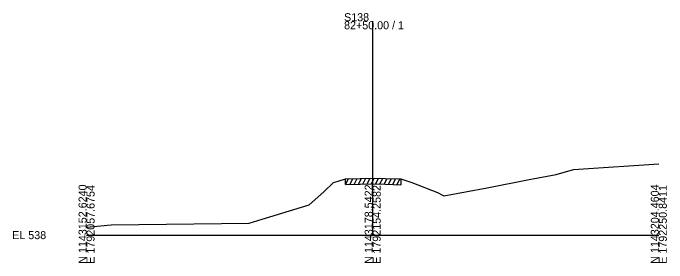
# Model space of a CAD drawing. Extents: x -26 to 1203, y -10 to 19606.
# Drawn here: x -25.7 to 202.8, y 4990.3 to 5077.5 of the extents above; entities that cross this region are included whole.
import ezdxf

# ---------------------------------------------------------------- set-up
doc = ezdxf.new("R2010")
doc.units = 0
for name, color, linetype in [('RD_EX_Driveway', 7, 'Continuous'), ('RD_GPK_XS_Cell', 7, 'Continuous'), ('RD_XS_ExGround', 7, 'Continuous'), ('RD_XS_ExPaveRet', 7, 'Continuous')]:
    doc.layers.add(name, color=color, linetype=linetype)

msp = doc.modelspace()

# ---------------------------------------------------------------- linework, layer by layer
at = {"layer": 'RD_GPK_XS_Cell'}
for p, q in [((100, 5000), (100, 5074.66)), ((0, 5000), (100, 5000)), ((100, 5000), (200, 5000))]:
    msp.add_line(p, q, dxfattribs=at)
at = {"layer": 'RD_XS_ExGround'}
msp.add_lwpolyline([(0, 5002.76), (8.62, 5003.55), (56.78, 5004.15), (61.42, 5005.57), (77.79, 5010.57), (82.91, 5015.17), (86.29, 5018.37), (87.96, 5018.85), (90.54, 5019.62), (95.57, 5019.77), (99.88, 5019.94), (104.36, 5019.79), (109.84, 5019.61), (111.6, 5019.06), (113.72, 5018.37), (122.64, 5014.83), (124.81, 5013.69), (139.97, 5016.47), (154.67, 5019.47), (164.08, 5021.21), (170.16, 5022.9), (171.91, 5022.99), (200, 5024.89)], dxfattribs=at)
at = {"layer": 'RD_XS_ExPaveRet'}
for p, q in [((90.54, 5017.62), (91.55, 5019.65)), ((90.54, 5017.62), (90.54, 5019.62)), ((92.04, 5017.66), (93.05, 5019.69)), ((93.54, 5017.71), (94.55, 5019.74)), ((95.04, 5017.75), (96.05, 5019.79)), ((96.54, 5017.81), (97.56, 5019.85)), ((98.04, 5017.87), (99.06, 5019.91)), ((99.54, 5017.92), (100.53, 5019.92)), ((101.04, 5017.9), (102.02, 5019.87)), ((102.54, 5017.85), (103.52, 5019.82)), ((104.04, 5017.8), (105.02, 5019.77)), ((105.54, 5017.75), (106.52, 5019.72)), ((107.04, 5017.7), (108.02, 5019.67)), ((108.54, 5017.65), (109.52, 5019.62)), ((109.84, 5019.61), (109.84, 5017.61)), ((90.54, 5017.62), (95.57, 5017.77)), ((95.57, 5017.77), (99.88, 5017.94)), ((99.88, 5017.94), (104.36, 5017.79)), ((104.36, 5017.79), (109.84, 5017.61))]:
    msp.add_line(p, q, dxfattribs=at)

# ---------------------------------------------------------------- texts
at = {"layer": 'RD_EX_Driveway'}
msp.add_text('547.97', height=0.0975, rotation=90, dxfattribs=at).set_placement((100.1, 5019.93))
at = {"layer": 'RD_GPK_XS_Cell'}
for s, p in [('S138', (90, 5074.66)), ('82+50.00 / 1', (90, 5071.86)), ('EL 538', (-26, 4998.6))]:
    msp.add_text(s, height=2.8, dxfattribs=at).set_placement(p)
for s, p in [('N 1143152.6240', (0, 4990)), ('E 1792057.6754', (2.8, 4990)), ('N 1143178.5422', (100, 4990)), ('E 1792154.2582', (102.8, 4990)), ('N 1143204.4604', (200, 4990)), ('E 1792250.8411', (202.8, 4990))]:
    msp.add_text(s, height=2.8, rotation=90, dxfattribs=at).set_placement(p)

doc.saveas('drawing.dxf')
